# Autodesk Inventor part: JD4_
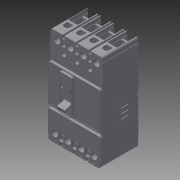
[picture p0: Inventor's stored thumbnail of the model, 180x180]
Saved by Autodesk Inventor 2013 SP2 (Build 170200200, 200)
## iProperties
Created: 2014-08
Part Number: JD4_
Material: Generic
Document SubType Name: Modeling
Designer: EM/EM
Density: 1 g/cm^3
Description: TYPE JD THERMAL MAGNETIC CIRCUIT BREAKERS FOUR POLE, SERIES C
MXEDIT: false
MXINVTNRV: INV Versioned Component|JD4_|004.0
Author: EM/EM
Revision Number: 004
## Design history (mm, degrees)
derived "JD4_.iam"
node "L1"
node "L2"
node "L3"
node "L4"
node "T1"
node "T2"
node "T3"
node "T4"
sketch "Sketch1"
  geometry: C1 r 10.795 at (8.89, 11.913) reference; C2 r 10.795 at (8.89, 11.913); 1 further point
  constraints: 1 centre point, 1 coincident, 1 concentric
extrude "Extrusion1" cut sketch "Sketch1" distance "d1" = 9.525; taper "d2" = 0 deg
sketch "Sketch2"
  geometry: C1 r 6.35 at (0, 0) reference; C2 r 6.35 at (0, 0); 1 further point
  constraints: 1 centre point, 1 coincident, 1 concentric
extrude "Extrusion2" cut sketch "Sketch2" distance "d3" = 9.525; taper "d5" = 0 deg; dims "d4" = 4.7752, "d6" = 0
sketch "Sketch3"
  geometry: C1 r 10.795 at (11.494, 11.913) reference; C2 r 10.795 at (11.494, 11.913); 1 further point
  constraints: 1 centre point, 1 coincident, 1 concentric
extrude "Extrusion3" cut sketch "Sketch3" distance "d7" = 9.525; taper "d8" = 0 deg
sketch "Sketch4"
  geometry: C1 r 6.35 at (0, 0) reference; C2 r 6.35 at (0, 0); 1 further point
  constraints: 1 centre point, 1 coincident, 1 concentric
extrude "Extrusion4" cut sketch "Sketch4" distance "d9" = 9.525; taper "d11" = 0 deg; dims "d10" = 4.7752, "d12" = 0
sketch "Sketch5"
  geometry: C1 r 10.795 at (11.494, 11.913) reference; C2 r 10.795 at (11.494, 11.913); 1 further point
  constraints: 1 centre point, 1 coincident, 1 concentric
extrude "Extrusion5" cut sketch "Sketch5" distance "d13" = 9.525; taper "d14" = 0 deg
sketch "Sketch6"
  geometry: C1 r 6.35 at (0, 0) reference; C2 r 6.35 at (0, 0); 1 further point
  constraints: 1 centre point, 1 coincident, 1 concentric
extrude "Extrusion6" cut sketch "Sketch6" distance "d15" = 9.525; taper "d17" = 0 deg; dims "d16" = 4.7752, "d18" = 0
sketch "Sketch7"
  geometry: C1 r 10.795 at (11.494, 11.913) reference; C2 r 10.795 at (11.494, 11.913); 1 further point
  constraints: 1 centre point, 1 coincident, 1 concentric
extrude "Extrusion7" cut sketch "Sketch7" distance "d19" = 9.525; taper "d20" = 0 deg
sketch "Sketch8"
  geometry: C1 r 6.35 at (0, 0) reference; C2 r 6.35 at (0, 0); 1 further point
  constraints: 1 centre point, 1 coincident, 1 concentric
extrude "Extrusion8" cut sketch "Sketch8" distance "d21" = 9.525; taper "d23" = 0 deg; dims "d22" = 4.7752, "d24" = 0
sketch "Sketch9"
  geometry: C1 r 8.738 at (-0.038, 0) reference; C2 r 8.738 at (-0.038, 0); 1 further point
  constraints: 1 centre point, 1 coincident, 1 concentric
extrude "Extrusion9" cut sketch "Sketch9" distance "d25" = 9.525; taper "d27" = 0 deg; dims "d26" = 9.5377, "d28" = 0
sketch "Sketch10"
  geometry: C1 r 8.738 at (-0.013, 0) reference; C2 r 8.738 at (-0.013, 0); 1 further point
  constraints: 1 centre point, 1 coincident, 1 concentric
extrude "Extrusion10" cut sketch "Sketch10" distance "d29" = 9.525; taper "d31" = 0 deg; dims "d30" = 4.7752, "d32" = 0
sketch "Sketch11"
  geometry: C1 r 8.738 at (-0.013, 0) reference; C2 r 8.738 at (-0.013, 0); 1 further point
  constraints: 1 centre point, 1 coincident, 1 concentric
extrude "Extrusion11" cut sketch "Sketch11" distance "d33" = 9.525; taper "d35" = 0 deg; dims "d34" = 4.7752, "d36" = 0
sketch "Sketch12"
  geometry: C1 r 8.738 at (0.013, 0) reference; C2 r 8.738 at (0.013, 0); 1 further point
  constraints: 1 centre point, 1 coincident, 1 concentric
extrude "Extrusion12" cut sketch "Sketch12" distance "d37" = 9.525; taper "d39" = 0 deg; dims "d38" = 4.7752, "d40" = 0
body "Solid1"
node "JD4_FIX.ipt:1"
node "JD4_FIX2.ipt:1"
body "Solid2"
